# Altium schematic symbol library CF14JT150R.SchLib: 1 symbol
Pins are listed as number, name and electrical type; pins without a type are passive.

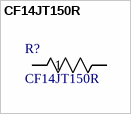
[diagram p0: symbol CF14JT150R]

## CF14JT150R
designator R?
Description; Manufacturer_Name: Stackpole International
footprint STA_CF14_STP
pins: 1, 2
